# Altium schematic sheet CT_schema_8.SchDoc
size 391 x 238 mm
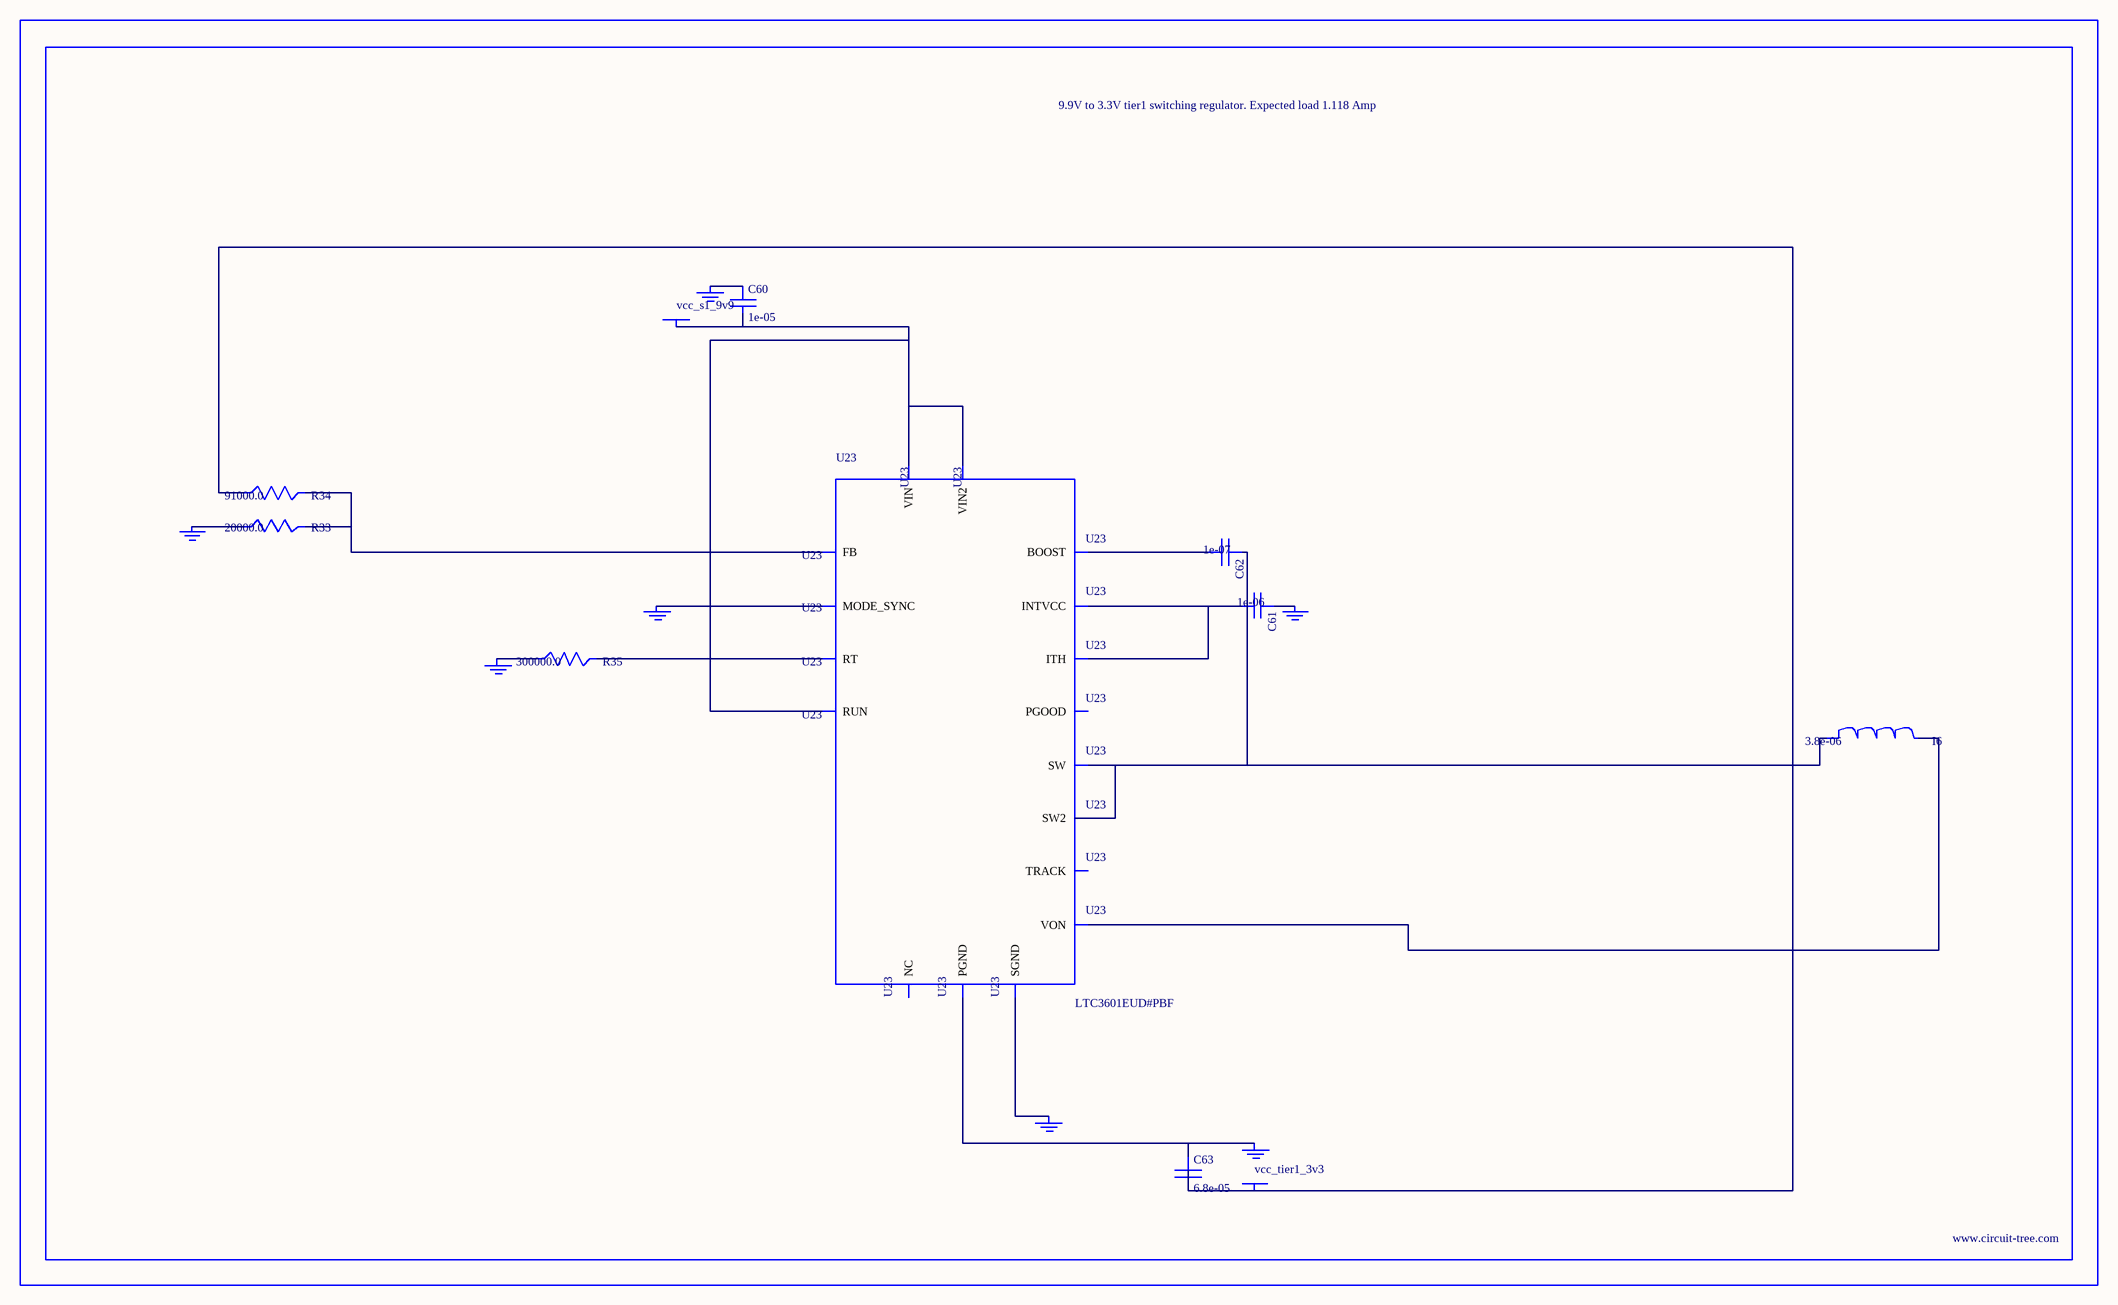
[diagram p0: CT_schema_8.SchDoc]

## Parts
BORDER7  (no value)
C60  1e-05  [C0805]
C61  1e-06  [C0603]
C62  1e-07  [C0402]
C63  6.8e-05  [2220]
GND_INSTANCE_7_0  (no value)
GND_INSTANCE_7_1  (no value)
GND_INSTANCE_7_2  (no value)
GND_INSTANCE_7_3  (no value)
GND_INSTANCE_7_4  (no value)
GND_INSTANCE_7_5  (no value)
GND_INSTANCE_7_6  (no value)
I6  3.8e-06  [DR1040]
POWER_INSTANCE_7_0  vcc_s1_9v9
POWER_INSTANCE_7_1  vcc_tier1_3v3
R33  20000.0  [R0603]
R34  91000.0  [R0603]
R35  300000.0  [R0603]
U23  LTC3601EUD#PBF  [QFN-16_EP]

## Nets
NetC60_1: C60.1 GND_INSTANCE_7_5.0(GND)
NetC60_2: C60.2 POWER_INSTANCE_7_0.0(PWR) U23.14(RUN) U23.15(VIN) U23.16(VIN2)
NetC61_1: C61.1 GND_INSTANCE_7_1.0(GND)
NetC61_2: C61.2 U23.7(INTVCC) U23.12(ITH)
NetC62_1: C62.1 I6.1 U23.3(SW) U23.4(SW2)
NetC62_2: C62.2 U23.6(BOOST)
NetC63_1: C63.1 GND_INSTANCE_7_6.0(GND) U23.17(PGND)
NetC63_2: C63.2 I6.2 POWER_INSTANCE_7_1.0(PWR) R34.1 U23.8(VON)
NetGND_INSTANCE_7_0_0: GND_INSTANCE_7_0.0(GND) U23.1(MODE_SYNC)
NetGND_INSTANCE_7_2_0: GND_INSTANCE_7_2.0(GND) U23.9(SGND)
NetGND_INSTANCE_7_3_0: GND_INSTANCE_7_3.0(GND) R35.1
NetGND_INSTANCE_7_4_0: GND_INSTANCE_7_4.0(GND) R33.1
NetR33_2: R33.2 R34.2 U23.11(FB)
NetR35_2: R35.2 U23.10(RT)

Not connected (* = marked no-connect by the designer): U23 2(PGOOD) 5(NC) 13(TRACK)

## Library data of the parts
BORDER7 = BORDER_PAGE7
C60 = C0805C106K8RACTU
C61 = C0603C105K3RACTU
C62 = C0402C104K3RACTU
C63 = C5750X5R1A686M
GND_INSTANCE_7_0-GND_INSTANCE_7_6 = GND
I6 = DR1040-3R8-R
POWER_INSTANCE_7_0 POWER_INSTANCE_7_1 = PWR
R33 = RC0603JR-0720KL
R34 = RC0603JR-0791KL
R35 = RC0603JR-07300KL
